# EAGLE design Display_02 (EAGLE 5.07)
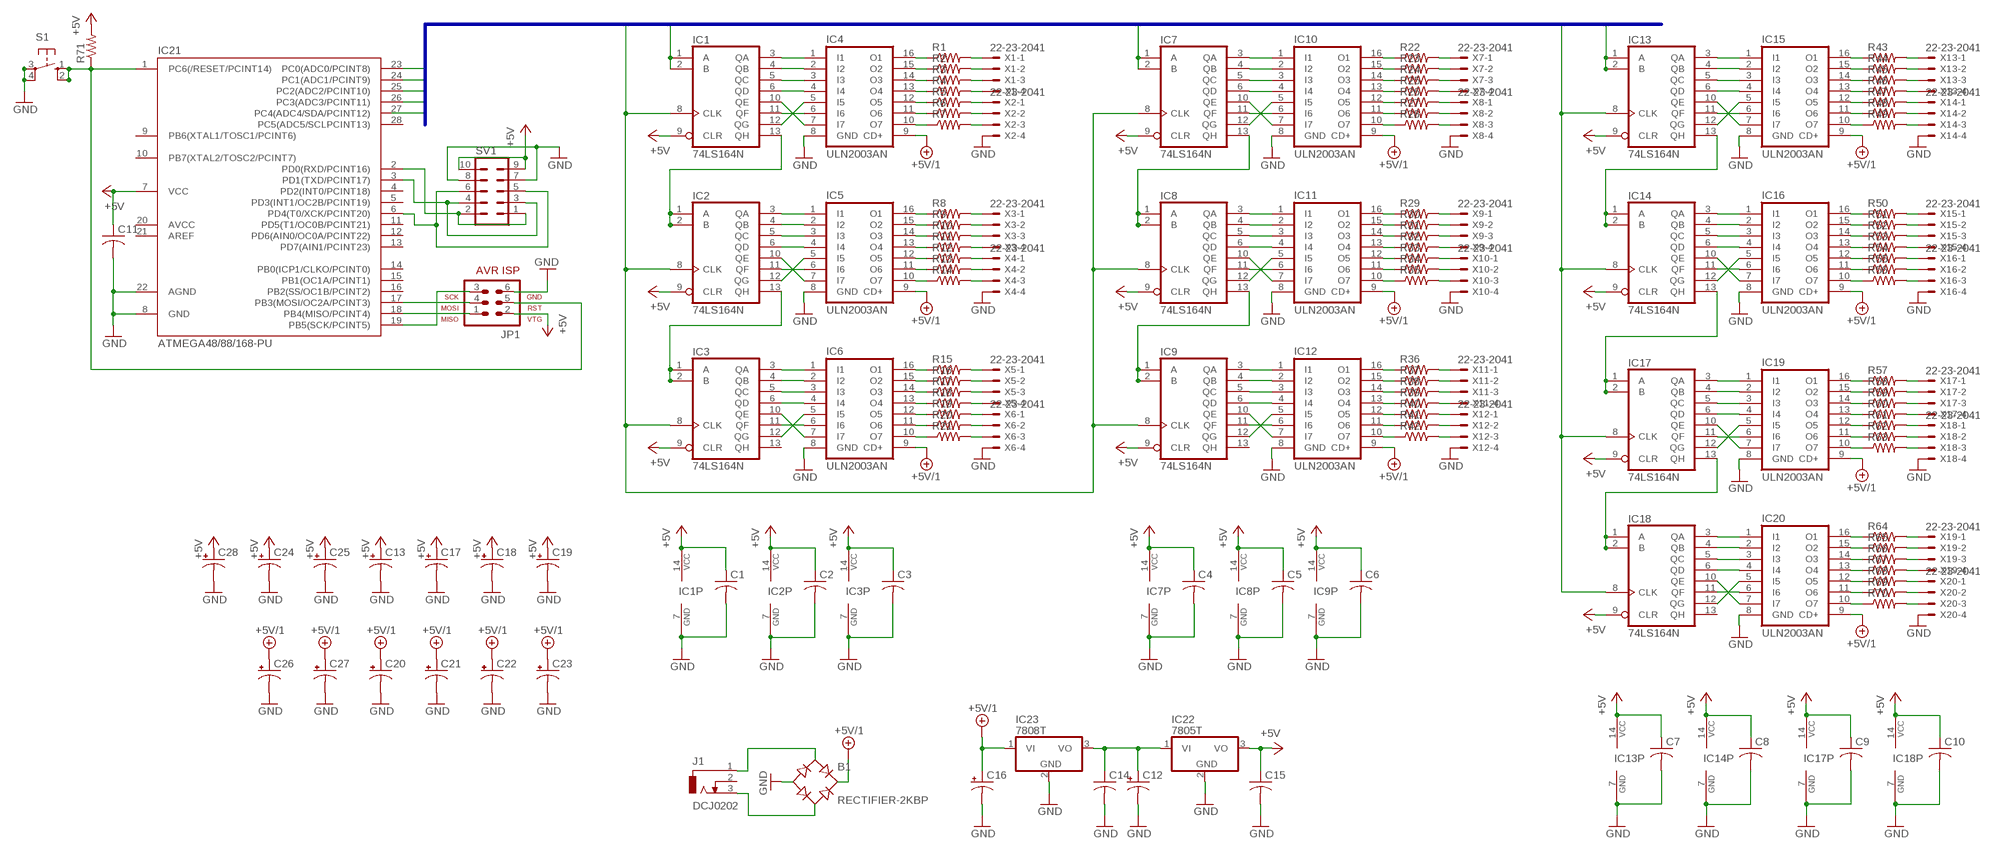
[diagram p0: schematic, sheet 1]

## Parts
B1  RECTIFIER-2KBP  [2KBP]
C1  C-US025-024X044  [C025-024X044]
C2  C-US025-024X044  [C025-024X044]
C3  C-US025-024X044  [C025-024X044]
C4  C-US025-024X044  [C025-024X044]
C5  C-US025-024X044  [C025-024X044]
C6  C-US025-024X044  [C025-024X044]
C7  C-US025-024X044  [C025-024X044]
C8  C-US025-024X044  [C025-024X044]
C9  C-US025-024X044  [C025-024X044]
C10  C-US025-024X044  [C025-024X044]
C11  C-US025-025X050  [C025-025X050]
C12  CPOL-USE2.5-7  [E2,5-7]
C13  CPOL-USE2.5-7  [E2,5-7]
C14  C-US025-030X050  [C025-030X050]
C15  C-US025-030X050  [C025-030X050]
C16  CPOL-USE2.5-7  [E2,5-7]
C17  CPOL-USE2.5-7  [E2,5-7]
C18  CPOL-USE2.5-7  [E2,5-7]
C19  CPOL-USE2.5-7  [E2,5-7]
C20  CPOL-USE2.5-7  [E2,5-7]
C21  CPOL-USE2.5-7  [E2,5-7]
C22  CPOL-USE2.5-7  [E2,5-7]
C23  CPOL-USE2.5-7  [E2,5-7]
C24  CPOL-USE2.5-7  [E2,5-7]
C25  CPOL-USE2.5-7  [E2,5-7]
C26  CPOL-USE2.5-7  [E2,5-7]
C27  CPOL-USE2.5-7  [E2,5-7]
C28  CPOL-USE2.5-7  [E2,5-7]
IC1  74LS164N  [DIL14]
IC2  74LS164N  [DIL14]
IC3  74LS164N  [DIL14]
IC4  ULN2003AN  [DIL16]
IC5  ULN2003AN  [DIL16]
IC6  ULN2003AN  [DIL16]
IC7  74LS164N  [DIL14]
IC8  74LS164N  [DIL14]
IC9  74LS164N  [DIL14]
IC10  ULN2003AN  [DIL16]
IC11  ULN2003AN  [DIL16]
IC12  ULN2003AN  [DIL16]
IC13  74LS164N  [DIL14]
IC14  74LS164N  [DIL14]
IC15  ULN2003AN  [DIL16]
IC16  ULN2003AN  [DIL16]
IC17  74LS164N  [DIL14]
IC18  74LS164N  [DIL14]
IC19  ULN2003AN  [DIL16]
IC20  ULN2003AN  [DIL16]
IC21  ATMEGA48/88/168-PU  [DIL28-3]
IC22  7805T  [TO220H]
IC23  7808T  [TO220H]
J1  DCJ0202  [DCJ0202]
JP1  AVR-ISP-6  [AVR-ISP-6]
R1  R-US_0204/7  [0204/7]
R2  R-US_0204/7  [0204/7]
R3  R-US_0204/7  [0204/7]
R4  R-US_0204/7  [0204/7]
R5  R-US_0204/7  [0204/7]
R6  R-US_0204/7  [0204/7]
R7  R-US_0204/7  [0204/7]
R8  R-US_0204/7  [0204/7]
R9  R-US_0204/7  [0204/7]
R10  R-US_0204/7  [0204/7]
R11  R-US_0204/7  [0204/7]
R12  R-US_0204/7  [0204/7]
R13  R-US_0204/7  [0204/7]
R14  R-US_0204/7  [0204/7]
R15  R-US_0204/7  [0204/7]
R16  R-US_0204/7  [0204/7]
R17  R-US_0204/7  [0204/7]
R18  R-US_0204/7  [0204/7]
R19  R-US_0204/7  [0204/7]
R20  R-US_0204/7  [0204/7]
R21  R-US_0204/7  [0204/7]
R22  R-US_0204/7  [0204/7]
R23  R-US_0204/7  [0204/7]
R24  R-US_0204/7  [0204/7]
R25  R-US_0204/7  [0204/7]
R26  R-US_0204/7  [0204/7]
R27  R-US_0204/7  [0204/7]
R28  R-US_0204/7  [0204/7]
R29  R-US_0204/7  [0204/7]
R30  R-US_0204/7  [0204/7]
R31  R-US_0204/7  [0204/7]
R32  R-US_0204/7  [0204/7]
R33  R-US_0204/7  [0204/7]
R34  R-US_0204/7  [0204/7]
R35  R-US_0204/7  [0204/7]
R36  R-US_0204/7  [0204/7]
R37  R-US_0204/7  [0204/7]
R38  R-US_0204/7  [0204/7]
R39  R-US_0204/7  [0204/7]
R40  R-US_0204/7  [0204/7]
R41  R-US_0204/7  [0204/7]
R42  R-US_0204/7  [0204/7]
R43  R-US_0204/7  [0204/7]
R44  R-US_0204/7  [0204/7]
R45  R-US_0204/7  [0204/7]
R46  R-US_0204/7  [0204/7]
R47  R-US_0204/7  [0204/7]
R48  R-US_0204/7  [0204/7]
R49  R-US_0204/7  [0204/7]
R50  R-US_0204/7  [0204/7]
R51  R-US_0204/7  [0204/7]
R52  R-US_0204/7  [0204/7]
R53  R-US_0204/7  [0204/7]
R54  R-US_0204/7  [0204/7]
R55  R-US_0204/7  [0204/7]
R56  R-US_0204/7  [0204/7]
R57  R-US_0204/7  [0204/7]
R58  R-US_0204/7  [0204/7]
R59  R-US_0204/7  [0204/7]
R60  R-US_0204/7  [0204/7]
R61  R-US_0204/7  [0204/7]
R62  R-US_0204/7  [0204/7]
R63  R-US_0204/7  [0204/7]
R64  R-US_0204/7  [0204/7]
R65  R-US_0204/7  [0204/7]
R66  R-US_0204/7  [0204/7]
R67  R-US_0204/7  [0204/7]
R68  R-US_0204/7  [0204/7]
R69  R-US_0204/7  [0204/7]
R70  R-US_0204/7  [0204/7]
R71  R-US_0204/7  [0204/7]
S1  10-XX  [B3F-10XX]
SV1  MA05-2  [MA05-2]
X1  22-23-2041  [22-23-2041]
X2  22-23-2041  [22-23-2041]
X3  22-23-2041  [22-23-2041]
X4  22-23-2041  [22-23-2041]
X5  22-23-2041  [22-23-2041]
X6  22-23-2041  [22-23-2041]
X7  22-23-2041  [22-23-2041]
X8  22-23-2041  [22-23-2041]
X9  22-23-2041  [22-23-2041]
X10  22-23-2041  [22-23-2041]
X11  22-23-2041  [22-23-2041]
X12  22-23-2041  [22-23-2041]
X13  22-23-2041  [22-23-2041]
X14  22-23-2041  [22-23-2041]
X15  22-23-2041  [22-23-2041]
X16  22-23-2041  [22-23-2041]
X17  22-23-2041  [22-23-2041]
X18  22-23-2041  [22-23-2041]
X19  22-23-2041  [22-23-2041]
X20  22-23-2041  [22-23-2041]

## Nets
+5V: C1.1 C2.1 C3.1 C4.1 C5.1 C6.1 C7.1 C8.1 C9.1 C10.1 C11.1 C13.+ C15.1 C17.+ C18.+ C19.+ C24.+ C25.+ C28.+ IC1.9(CLR) IC1.14(VCC) IC2.9(CLR) IC2.14(VCC) IC3.9(CLR) IC3.14(VCC) IC7.9(CLR) IC7.14(VCC) IC8.9(CLR) IC8.14(VCC) IC9.9(CLR) IC9.14(VCC) IC13.9(CLR) IC13.14(VCC) IC14.9(CLR) IC14.14(VCC) IC17.9(CLR) IC17.14(VCC) IC18.9(CLR) IC18.14(VCC) IC21.7(VCC) IC22.3(VO) JP1.2 R71.2 SV1.9 SV1.10
+5V/1: B1.+ C16.+ C20.+ C21.+ C22.+ C23.+ C26.+ C27.+ IC4.9(CD+) IC5.9(CD+) IC6.9(CD+) IC10.9(CD+) IC11.9(CD+) IC12.9(CD+) IC15.9(CD+) IC16.9(CD+) IC19.9(CD+) IC20.9(CD+) IC23.1(VI)
GND: B1.- C1.2 C2.2 C3.2 C4.2 C5.2 C6.2 C7.2 C8.2 C9.2 C10.2 C11.2 C12.- C13.- C14.2 C15.2 C16.- C17.- C18.- C19.- C20.- C21.- C22.- C23.- C24.- C25.- C26.- C27.- C28.- IC1.7(GND) IC2.7(GND) IC3.7(GND) IC4.8(GND) IC5.8(GND) IC6.8(GND) IC7.7(GND) IC8.7(GND) IC9.7(GND) IC10.8(GND) IC11.8(GND) IC12.8(GND) IC13.7(GND) IC14.7(GND) IC15.8(GND) IC16.8(GND) IC17.7(GND) IC18.7(GND) IC19.8(GND) IC20.8(GND) IC21.8(GND) IC21.22(AGND) IC22.2(GND) IC23.2(GND) JP1.6 S1.3(P) S1.4(P1) SV1.7 SV1.8 X2.4 X4.4 X6.4 X8.4 X10.4 X12.4 X14.4 X16.4 X18.4 X20.4
N$1: IC1.3(QA) IC4.1(I1)
N$2: IC1.4(QB) IC4.2(I2)
N$3: IC1.5(QC) IC4.3(I3)
N$4: IC1.6(QD) IC4.4(I4)
N$5: IC1.10(QE) IC4.7(I7)
N$6: IC1.11(QF) IC4.6(I6)
N$7: IC1.12(QG) IC4.5(I5)
N$8: IC2.3(QA) IC5.1(I1)
N$9: IC2.4(QB) IC5.2(I2)
N$10: IC2.5(QC) IC5.3(I3)
N$11: IC2.6(QD) IC5.4(I4)
N$12: IC2.10(QE) IC5.7(I7)
N$13: IC2.12(QG) IC5.5(I5)
N$14: IC2.11(QF) IC5.6(I6)
N$15: IC3.3(QA) IC6.1(I1)
N$16: IC3.4(QB) IC6.2(I2)
N$17: IC4.16(O1) R1.1
N$18: IC4.15(O2) R2.1
N$19: IC4.14(O3) R3.1
N$20: IC4.13(O4) R4.1
N$21: IC4.12(O5) R5.1
N$22: IC4.11(O6) R6.1
N$23: IC4.10(O7) R7.1
N$24: R1.2 X1.1
N$25: R2.2 X1.2
N$26: R3.2 X1.3
N$27: R4.2 X1.4
N$28: R5.2 X2.1
N$29: R6.2 X2.2
N$30: R7.2 X2.3
N$31: IC5.16(O1) R8.1
N$32: IC5.15(O2) R9.1
N$33: IC5.14(O3) R10.1
N$34: IC5.13(O4) R11.1
N$35: IC5.12(O5) R12.1
N$36: IC5.11(O6) R13.1
N$37: IC5.10(O7) R14.1
N$38: R8.2 X3.1
N$39: R9.2 X3.2
N$40: R10.2 X3.3
N$41: R11.2 X3.4
N$42: R12.2 X4.1
N$43: R13.2 X4.2
N$44: R14.2 X4.3
N$45: IC6.16(O1) R15.1
N$46: IC6.15(O2) R16.1
N$47: IC6.14(O3) R17.1
N$48: IC6.13(O4) R18.1
N$49: IC6.12(O5) R19.1
N$50: IC6.11(O6) R20.1
N$51: IC6.10(O7) R21.1
N$52: R15.2 X5.1
N$53: R16.2 X5.2
N$54: R17.2 X5.3
N$55: R18.2 X5.4
N$56: R19.2 X6.1
N$57: R20.2 X6.2
N$58: R21.2 X6.3
N$59: IC21.2(PD0(RXD/PCINT16)) SV1.1 SV1.2
N$60: IC21.3(PD1(TXD/PCINT17)) SV1.3 SV1.4
N$61: IC3.5(QC) IC6.3(I3)
N$62: IC3.6(QD) IC6.4(I4)
N$63: IC3.10(QE) IC6.7(I7)
N$64: IC3.12(QG) IC6.5(I5)
N$65: IC3.11(QF) IC6.6(I6)
N$66: IC10.16(O1) R22.1
N$67: IC2.13(QH) IC3.1(A) IC3.2(B)
N$68: IC1.13(QH) IC2.1(A) IC2.2(B)
N$69: IC10.15(O2) R23.1
N$70: IC10.14(O3) R24.1
N$71: IC10.13(O4) R25.1
N$72: IC10.12(O5) R26.1
N$73: IC10.11(O6) R27.1
N$74: IC10.10(O7) R28.1
N$75: R22.2 X7.1
N$76: R23.2 X7.2
N$77: R24.2 X7.3
N$78: R25.2 X7.4
N$79: R26.2 X8.1
N$80: R27.2 X8.2
N$81: R28.2 X8.3
N$82: IC11.16(O1) R29.1
N$83: IC11.15(O2) R30.1
N$84: IC11.14(O3) R31.1
N$85: IC11.13(O4) R32.1
N$86: IC11.12(O5) R33.1
N$87: IC11.11(O6) R34.1
N$88: IC11.10(O7) R35.1
N$89: R29.2 X9.1
N$90: R30.2 X9.2
N$91: R31.2 X9.3
N$92: R32.2 X9.4
N$93: R33.2 X10.1
N$94: R34.2 X10.2
N$95: R35.2 X10.3
N$96: IC12.16(O1) R36.1
N$97: IC12.15(O2) R37.1
N$98: IC12.14(O3) R38.1
N$99: IC12.13(O4) R39.1
N$100: IC12.12(O5) R40.1
N$101: IC12.11(O6) R41.1
N$102: IC12.10(O7) R42.1
N$103: R36.2 X11.1
N$104: R37.2 X11.2
N$105: R38.2 X11.3
N$106: R39.2 X11.4
N$107: R40.2 X12.1
N$108: R41.2 X12.2
N$109: R42.2 X12.3
N$110: IC8.13(QH) IC9.1(A) IC9.2(B)
N$111: IC7.13(QH) IC8.1(A) IC8.2(B)
N$112: IC15.16(O1) R43.1
N$113: IC21.6(PD4(T0/XCK/PCINT20)) SV1.5 SV1.6
N$114: IC7.6(QD) IC10.4(I4)
N$115: IC7.5(QC) IC10.3(I3)
N$116: IC7.4(QB) IC10.2(I2)
N$117: IC7.3(QA) IC10.1(I1)
N$118: IC7.10(QE) IC10.7(I7)
N$119: IC7.11(QF) IC10.6(I6)
N$120: IC7.12(QG) IC10.5(I5)
N$121: IC8.3(QA) IC11.1(I1)
N$122: IC8.4(QB) IC11.2(I2)
N$123: IC8.5(QC) IC11.3(I3)
N$124: IC8.6(QD) IC11.4(I4)
N$125: IC8.10(QE) IC11.7(I7)
N$126: IC8.12(QG) IC11.5(I5)
N$127: IC8.11(QF) IC11.6(I6)
N$128: IC9.3(QA) IC12.1(I1)
N$129: IC9.4(QB) IC12.2(I2)
N$130: IC9.5(QC) IC12.3(I3)
N$131: IC9.6(QD) IC12.4(I4)
N$132: IC9.10(QE) IC12.7(I7)
N$133: IC9.12(QG) IC12.5(I5)
N$134: IC9.11(QF) IC12.6(I6)
N$135: IC15.15(O2) R44.1
N$136: IC15.14(O3) R45.1
N$137: IC15.13(O4) R46.1
N$138: IC15.12(O5) R47.1
N$139: IC15.11(O6) R48.1
N$140: IC15.10(O7) R49.1
N$141: R43.2 X13.1
N$142: R44.2 X13.2
N$143: R45.2 X13.3
N$144: R46.2 X13.4
N$145: R47.2 X14.1
N$146: R48.2 X14.2
N$147: R49.2 X14.3
N$148: IC16.16(O1) R50.1
N$149: IC16.15(O2) R51.1
N$150: IC16.14(O3) R52.1
N$151: IC16.13(O4) R53.1
N$152: IC16.12(O5) R54.1
N$153: IC16.11(O6) R55.1
N$154: IC16.10(O7) R56.1
N$155: R50.2 X15.1
N$156: R51.2 X15.2
N$157: R52.2 X15.3
N$158: R53.2 X15.4
N$159: R54.2 X16.1
N$160: R55.2 X16.2
N$161: R56.2 X16.3
N$162: IC13.13(QH) IC14.1(A) IC14.2(B)
N$165: IC13.10(QE) IC15.7(I7)
N$166: IC13.12(QG) IC15.5(I5)
N$167: IC13.11(QF) IC15.6(I6)
N$168: IC14.10(QE) IC16.7(I7)
N$169: IC14.12(QG) IC16.5(I5)
N$170: IC14.11(QF) IC16.6(I6)
N$171: IC13.3(QA) IC15.1(I1)
N$172: IC13.4(QB) IC15.2(I2)
N$173: IC13.5(QC) IC15.3(I3)
N$174: IC13.6(QD) IC15.4(I4)
N$175: IC14.3(QA) IC16.1(I1)
N$176: IC14.4(QB) IC16.2(I2)
N$177: IC14.5(QC) IC16.3(I3)
N$178: IC14.6(QD) IC16.4(I4)
N$179: IC19.16(O1) R57.1
N$180: IC19.15(O2) R58.1
N$181: IC19.14(O3) R59.1
N$182: IC19.13(O4) R60.1
N$183: IC19.12(O5) R61.1
N$184: IC19.11(O6) R62.1
N$185: IC19.10(O7) R63.1
N$186: R57.2 X17.1
N$187: R58.2 X17.2
N$188: R59.2 X17.3
N$189: R60.2 X17.4
N$190: R61.2 X18.1
N$191: R62.2 X18.2
N$192: R63.2 X18.3
N$193: IC20.16(O1) R64.1
N$194: IC20.15(O2) R65.1
N$195: IC20.14(O3) R66.1
N$196: IC20.13(O4) R67.1
N$197: IC20.12(O5) R68.1
N$198: IC20.11(O6) R69.1
N$199: IC20.10(O7) R70.1
N$200: R64.2 X19.1
N$201: R65.2 X19.2
N$202: R66.2 X19.3
N$203: R67.2 X19.4
N$204: R68.2 X20.1
N$205: R69.2 X20.2
N$206: R70.2 X20.3
N$207: IC17.13(QH) IC18.1(A) IC18.2(B)
N$208: IC14.13(QH) IC17.1(A) IC17.2(B)
N$209: IC21.18(PB4(MISO/PCINT4)) JP1.1
N$210: IC17.10(QE) IC19.7(I7)
N$211: IC17.12(QG) IC19.5(I5)
N$212: IC17.11(QF) IC19.6(I6)
N$213: IC18.10(QE) IC20.7(I7)
N$214: IC18.12(QG) IC20.5(I5)
N$215: IC18.11(QF) IC20.6(I6)
N$216: IC17.3(QA) IC19.1(I1)
N$217: IC17.4(QB) IC19.2(I2)
N$218: IC17.5(QC) IC19.3(I3)
N$219: IC17.6(QD) IC19.4(I4)
N$220: IC18.3(QA) IC20.1(I1)
N$221: IC18.4(QB) IC20.2(I2)
N$222: IC18.5(QC) IC20.3(I3)
N$223: IC18.6(QD) IC20.4(I4)
N$224: IC21.17(PB3(MOSI/OC2A/PCINT3)) JP1.4
N$225: IC21.19(PB5(SCK/PCINT5)) JP1.3
N$226: IC21.1(PC6(/RESET/PCINT14)) JP1.5 R71.1 S1.1(S) S1.2(S1)
N$227: C12.+ C14.1 IC22.1(VI) IC23.3(VO)
N$228: B1.AC2 J1.3
N$229: B1.AC1 J1.1
PORTC0: IC13.1(A) IC13.2(B) IC21.23(PC0(ADC0/PCINT8))
PORTC1: IC13.8(CLK) IC14.8(CLK) IC17.8(CLK) IC18.8(CLK) IC21.24(PC1(ADC1/PCINT9))
PORTC2: IC7.1(A) IC7.2(B) IC21.25(PC2(ADC2/PCINT10))
PORTC3: IC1.1(A) IC1.2(B) IC21.26(PC3(ADC3/PCINT11))
PORTC4: IC1.8(CLK) IC2.8(CLK) IC3.8(CLK) IC7.8(CLK) IC8.8(CLK) IC9.8(CLK)
Unconnected: IC3.13(QH) IC9.13(QH) IC18.13(QH) IC21.4(PD2(INT0/PCINT18)) IC21.5(PD3(INT1/OC2B/PCINT19)) IC21.9(PB6(XTAL1/TOSC1/PCINT6)) IC21.10(PB7(XTAL2/TOSC2/PCINT7)) IC21.11(PD5(T1/OC0B/PCINT21)) IC21.12(PD6(AIN0/OC0A/PCINT22)) IC21.13(PD7(AIN1/PCINT23)) IC21.14(PB0(ICP1/CLKO/PCINT0)) IC21.15(PB1(OC1A/PCINT1)) IC21.16(PB2(SS/OC1B/PCINT2)) IC21.20(AVCC) IC21.21(AREF) IC21.27(PC4(ADC4/SDA/PCINT12)) IC21.28(PC5(ADC5/SCLPCINT13)) J1.2

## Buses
PORTC[0..5]

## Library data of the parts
B1 = rectifier:RECTIFIER-: Rectifier
C1-C10 C14 C15 = rcl:C-US: CAPACITOR, American symbol
C11 = resistor:C-US: CAPACITOR, American symbol
C12 C13 C16-C28 = rcl:CPOL-US: POLARIZED CAPACITOR, American symbol
IC1-IC3 IC7-IC9 IC13 IC14 IC17 IC18 = 74xx-us:74*164: 8-bit parallel out SHIFT REGISTER
IC4-IC6 IC10-IC12 IC15 IC16 IC19 IC20 = uln-udn:ULN2003A: DRIVER ARRAY
IC21 = atmega8:ATMEGA48/88/168-PU
IC22 IC23 = linear:78*: Positive VOLTAGE REGULATOR Source: http://cache.national.com/ds/LM/LM78L05.pdf http://www.fairchildsemi.com/ds/LM/LM7805.pdf
J1 = con-jack:DCJ0202: DC POWER JACK Source: DCJ0202.pdf
JP1 = avr-6:AVR-ISP-6: AVR ISP-6 Serial Programming Header
R1-R71 = rcl:R-US_: RESISTOR, American symbol
S1 = switch-omron:10-XX: OMRON SWITCH
SV1 = con-lstb:MA05-2: PIN HEADER
X1-X20 = con-molex:22-23-2041: .100" (2.54mm) Center Header - 4 Pin

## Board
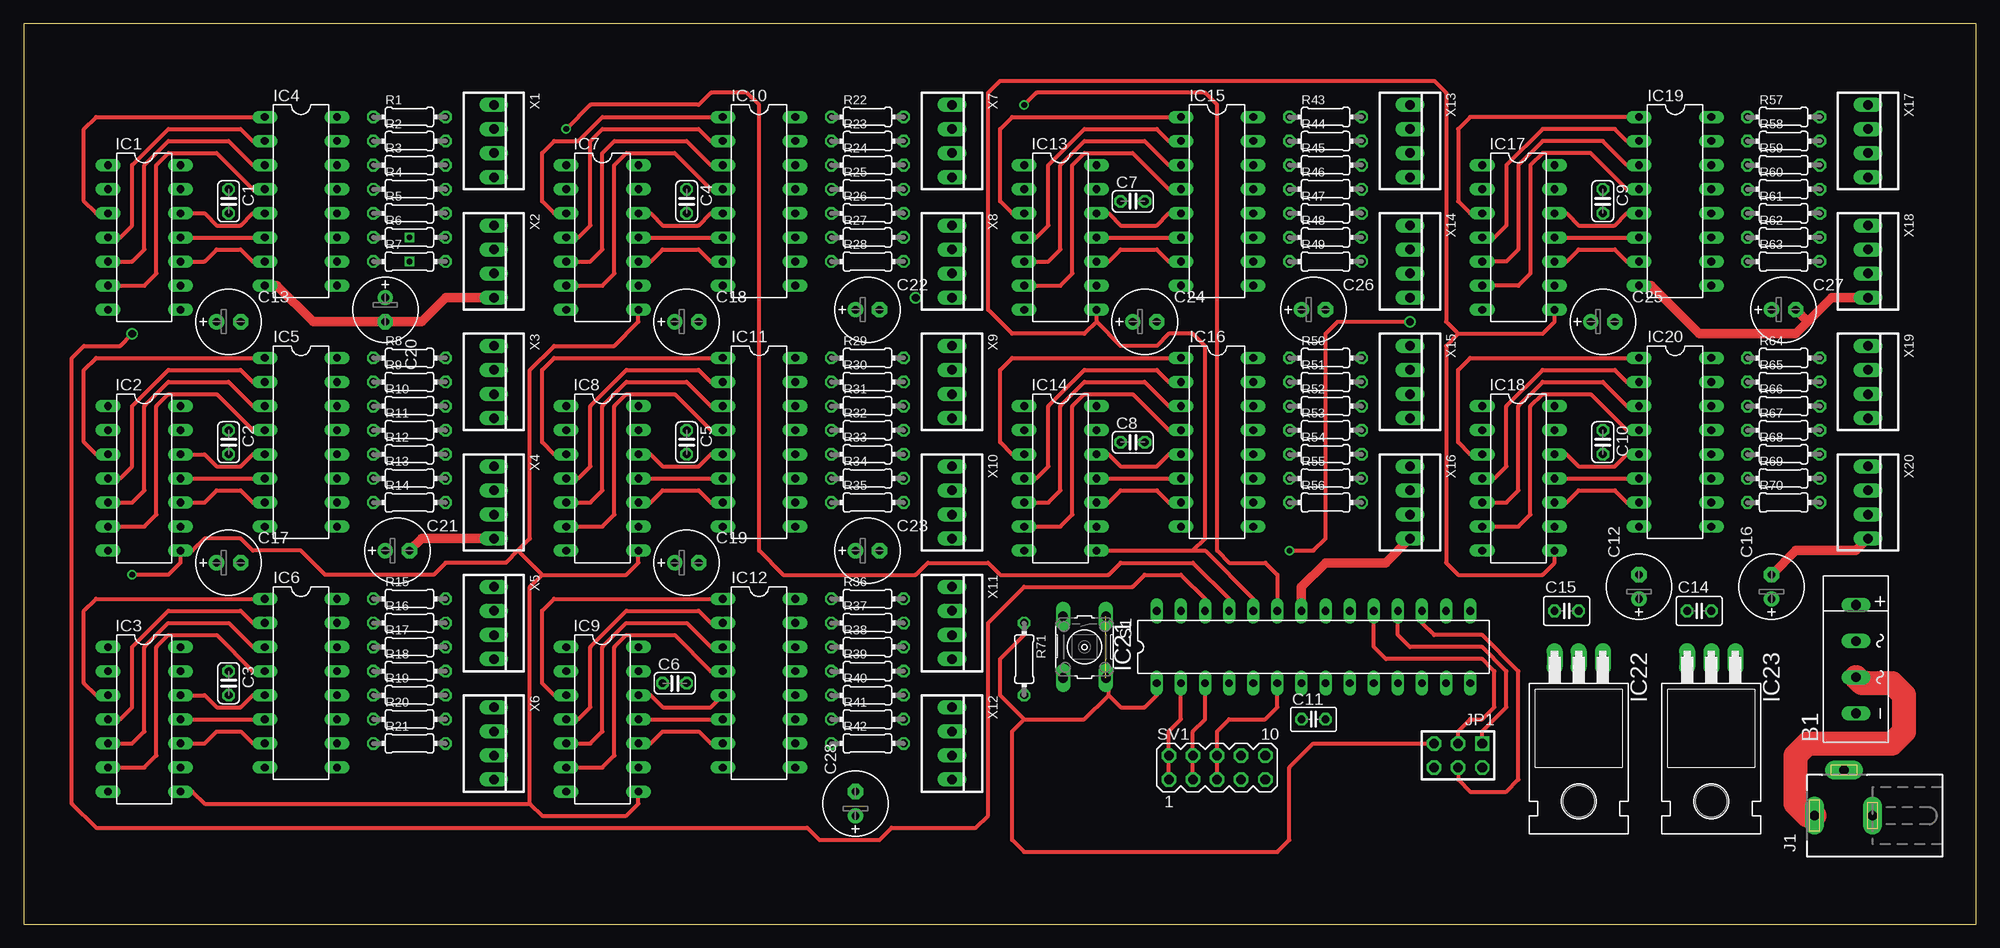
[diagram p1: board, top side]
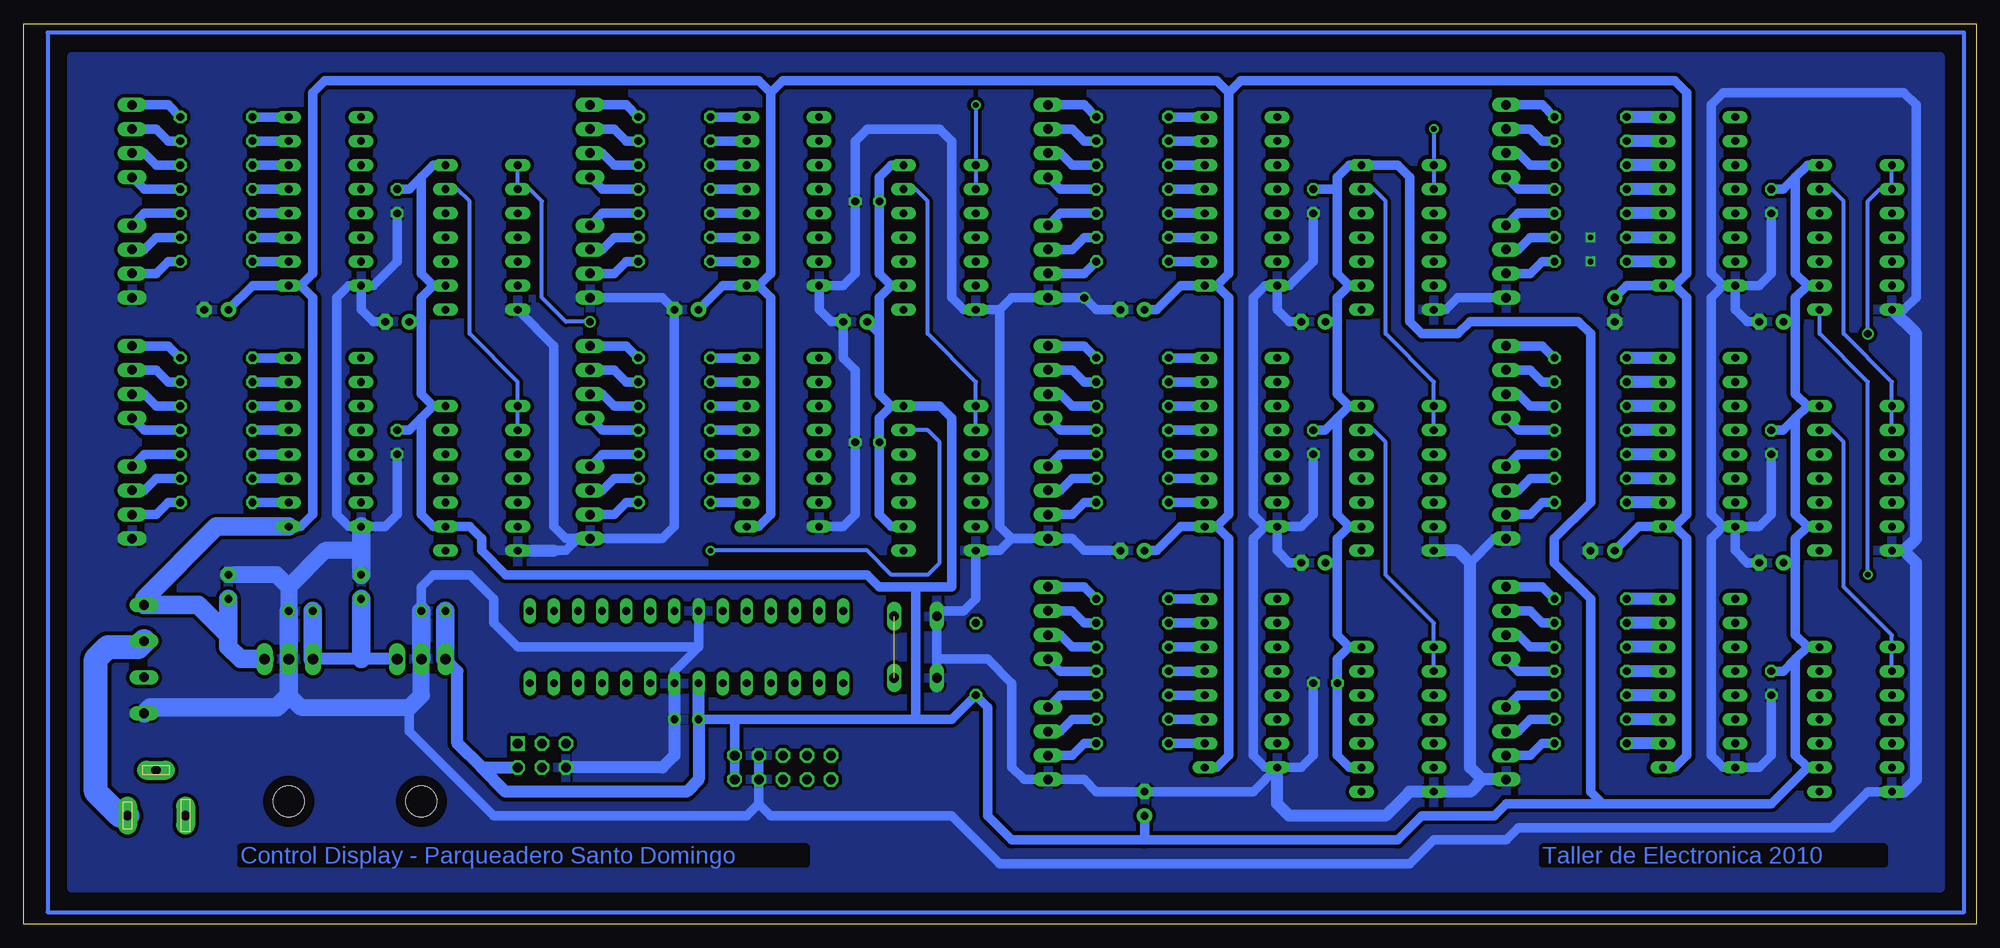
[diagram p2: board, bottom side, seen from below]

Size 205.72 x 94.92 mm. Coordinates in mm from the lower left corner, seen from the top.
Outline: 0,0 205.72,0 205.72,94.92 0,94.92 0,0
Copper layers (1*16): Top 0.035mm / dielectric 1.5mm / Bottom 0.035mm
Design rules "default *": minimum track width 15mil, minimum drill 24mil, track to track 15mil, track to pad 15mil, pad to pad 15mil, via to via 15mil, smd to smd 8mil, copper to edge 40mil, drill to drill 8mil, minimum pad ring 10mil, minimum via ring 8mil, stop-mask expansion 4mil, vias tented up to drill 0mil, thermal gap 10mil

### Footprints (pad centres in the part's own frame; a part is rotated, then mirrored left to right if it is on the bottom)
2KBP = drill 1.016 long: + 5.715,0; - -5.715,0; AC1 -1.905,0; AC2 1.905,0
C025-024X044 = drill 0.813 octagon: 1 -1.27,0; 2 1.27,0
C025-025X050 = drill 0.813 octagon: 1 -1.27,0; 2 1.27,0
E2,5-7 = drill 0.813 pad 1.6 round: + -1.27,0 | drill 0.813 pad 1.6 octagon: - 1.27,0
C025-030X050 = drill 0.813 octagon: 1 -1.27,0; 2 1.27,0
DIL14 = drill 0.813 long: 1 -7.62,-3.81; 2 -5.08,-3.81; 3 -2.54,-3.81; 4 0,-3.81; 5 2.54,-3.81; 6 5.08,-3.81; 7 7.62,-3.81; 8 7.62,3.81; 9 5.08,3.81; 10 2.54,3.81; 11 0,3.81; 12 -2.54,3.81; 13 -5.08,3.81; 14 -7.62,3.81
DIL16 = drill 0.813 long: 1 -8.89,-3.81; 2 -6.35,-3.81; 3 -3.81,-3.81; 4 -1.27,-3.81; 5 1.27,-3.81; 6 3.81,-3.81; 7 6.35,-3.81; 8 8.89,-3.81; 9 8.89,3.81; 10 6.35,3.81; 11 3.81,3.81; 12 1.27,3.81; 13 -1.27,3.81; 14 -3.81,3.81; 15 -6.35,3.81; 16 -8.89,3.81
DIL28-3 = drill 0.813 long: 1 -16.51,-3.81; 2 -13.97,-3.81; 3 -11.43,-3.81; 4 -8.89,-3.81; 5 -6.35,-3.81; 6 -3.81,-3.81; 7 -1.27,-3.81; 8 1.27,-3.81; 9 3.81,-3.81; 10 6.35,-3.81; 11 8.89,-3.81; 12 11.43,-3.81; 13 13.97,-3.81; 14 16.51,-3.81; 15 16.51,3.81; 16 13.97,3.81; 17 11.43,3.81; 18 8.89,3.81; 19 6.35,3.81; 20 3.81,3.81; 21 1.27,3.81; 22 -1.27,3.81; 23 -3.81,3.81; 24 -6.35,3.81; 25 -8.89,3.81; 26 -11.43,3.81; 27 -13.97,3.81; 28 -16.51,3.81
TO220H = drill 1.118 long: 1 -2.54,-10.16; 2 0,-10.16; 3 2.54,-10.16 | hole 3.302: 0,4.826
DCJ0202 = drill 1 pad 2 long: 1 0,3.1; 2 4.8,0; 3 0,-3
AVR-ISP-6 = drill 1.016 square: 1 -2.54,-1.27 | drill 1.016 octagon: 2 -2.54,1.27; 3 0,-1.27; 4 0,1.27; 5 2.54,-1.27; 6 2.54,1.27
0204/7 = drill 0.813 octagon: 1 -3.81,0; 2 3.81,0
B3F-10XX = drill 1.016 long: 1 -3.251,2.261; 2 3.251,2.261; 3 -3.251,-2.261; 4 3.251,-2.261
MA05-2 = drill 1.016 octagon: 1 -5.08,-1.27; 2 -5.08,1.27; 3 -2.54,-1.27; 4 -2.54,1.27; 5 0,-1.27; 6 0,1.27; 7 2.54,-1.27; 8 2.54,1.27; 9 5.08,-1.27; 10 5.08,1.27
22-23-2041 = drill 1 long: 1 -3.81,0; 2 -1.27,0; 3 1.27,0; 4 3.81,0

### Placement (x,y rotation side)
B1  193.04,27.94 90 top
C1  21.59,76.2 270 top
C2  21.59,50.8 270 top
C3  21.59,25.4 270 top
C4  69.85,76.2 270 top
C5  69.85,50.8 270 top
C6  68.58,25.4 0 top
C7  116.84,76.2 0 top
C8  116.84,50.8 0 top
C9  166.37,76.2 270 top
C10  166.37,50.8 270 top
C11  135.89,21.59 0 top
C12  170.18,35.56 90 top
C13  21.59,63.5 0 top
C14  176.53,33.02 0 top
C15  162.56,33.02 0 top
C16  184.15,35.56 90 top
C17  21.59,38.1 0 top
C18  69.85,63.5 0 top
C19  69.85,38.1 0 top
C20  38.1,64.77 270 top
C21  39.37,39.37 0 top
C22  88.9,64.77 0 top
C23  88.9,39.37 0 top
C24  118.11,63.5 0 top
C25  166.37,63.5 0 top
C26  135.89,64.77 0 top
C27  185.42,64.77 0 top
C28  87.63,12.7 90 top
IC1  12.7,72.39 270 top
IC2  12.7,46.99 270 top
IC3  12.7,21.59 270 top
IC4  29.21,76.2 270 top
IC5  29.21,50.8 270 top
IC6  29.21,25.4 270 top
IC7  60.96,72.39 270 top
IC8  60.96,46.99 270 top
IC9  60.96,21.59 270 top
IC10  77.47,76.2 270 top
IC11  77.47,50.8 270 top
IC12  77.47,25.4 270 top
IC13  109.22,72.39 270 top
IC14  109.22,46.99 270 top
IC15  125.73,76.2 270 top
IC16  125.73,50.8 270 top
IC17  157.48,72.39 270 top
IC18  157.48,46.99 270 top
IC19  173.99,76.2 270 top
IC20  173.99,50.8 270 top
IC21  135.89,29.21 0 top
IC22  163.83,17.78 180 top
IC23  177.8,17.78 180 top
J1  191.77,11.43 90 top
JP1  151.13,17.78 180 top
R1  40.64,85.09 0 top
R2  40.64,82.55 0 top
R3  40.64,80.01 0 top
R4  40.64,77.47 0 top
R5  40.64,74.93 0 top
R6  40.64,72.39 0 top
R7  40.64,69.85 0 top
R8  40.64,59.69 0 top
R9  40.64,57.15 0 top
R10  40.64,54.61 0 top
R11  40.64,52.07 0 top
R12  40.64,49.53 0 top
R13  40.64,46.99 0 top
R14  40.64,44.45 0 top
R15  40.64,34.29 0 top
R16  40.64,31.75 0 top
R17  40.64,29.21 0 top
R18  40.64,26.67 0 top
R19  40.64,24.13 0 top
R20  40.64,21.59 0 top
R21  40.64,19.05 0 top
R22  88.9,85.09 0 top
R23  88.9,82.55 0 top
R24  88.9,80.01 0 top
R25  88.9,77.47 0 top
R26  88.9,74.93 0 top
R27  88.9,72.39 0 top
R28  88.9,69.85 0 top
R29  88.9,59.69 0 top
R30  88.9,57.15 0 top
R31  88.9,54.61 0 top
R32  88.9,52.07 0 top
R33  88.9,49.53 0 top
R34  88.9,46.99 0 top
R35  88.9,44.45 0 top
R36  88.9,34.29 0 top
R37  88.9,31.75 0 top
R38  88.9,29.21 0 top
R39  88.9,26.67 0 top
R40  88.9,24.13 0 top
R41  88.9,21.59 0 top
R42  88.9,19.05 0 top
R43  137.16,85.09 0 top
R44  137.16,82.55 0 top
R45  137.16,80.01 0 top
R46  137.16,77.47 0 top
R47  137.16,74.93 0 top
R48  137.16,72.39 0 top
R49  137.16,69.85 0 top
R50  137.16,59.69 0 top
R51  137.16,57.15 0 top
R52  137.16,54.61 0 top
R53  137.16,52.07 0 top
R54  137.16,49.53 0 top
R55  137.16,46.99 0 top
R56  137.16,44.45 0 top
R57  185.42,85.09 0 top
R58  185.42,82.55 0 top
R59  185.42,80.01 0 top
R60  185.42,77.47 0 top
R61  185.42,74.93 0 top
R62  185.42,72.39 0 top
R63  185.42,69.85 0 top
R64  185.42,59.69 0 top
R65  185.42,57.15 0 top
R66  185.42,54.61 0 top
R67  185.42,52.07 0 top
R68  185.42,49.53 0 top
R69  185.42,46.99 0 top
R70  185.42,44.45 0 top
R71  105.41,27.94 270 top
S1  111.76,29.21 270 top
SV1  125.73,16.51 0 top
X1  49.53,82.55 270 top
X2  49.53,69.85 270 top
X3  49.53,57.15 270 top
X4  49.53,44.45 270 top
X5  49.53,31.75 270 top
X6  49.53,19.05 270 top
X7  97.79,82.55 270 top
X8  97.79,69.85 270 top
X9  97.79,57.15 270 top
X10  97.79,44.45 270 top
X11  97.79,31.75 270 top
X12  97.79,19.05 270 top
X13  146.05,82.55 270 top
X14  146.05,69.85 270 top
X15  146.05,57.15 270 top
X16  146.05,44.45 270 top
X17  194.31,82.55 270 top
X18  194.31,69.85 270 top
X19  194.31,57.15 270 top
X20  194.31,44.45 270 top

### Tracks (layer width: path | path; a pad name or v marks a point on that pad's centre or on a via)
+5V
  Bottom 1.016: IC13.14 114.3,80.01 115.57,78.74 C7.1 115.57,68.58 114.3,67.31 | 114.3,67.31 IC13.9 | 114.3,67.31 115.57,66.04 115.57,62.23 | 115.57,62.23 115.57,55.88 114.3,54.61 | 162.56,67.31 163.83,68.58 163.83,78.74 | 163.83,78.74 162.56,80.01 IC17.14 | 162.56,67.31 IC17.9 | 162.56,67.31 163.83,66.04 163.83,63.5 | 163.83,63.5 163.83,55.88 162.56,54.61 | 162.56,54.61 IC18.14 | 163.83,53.34 162.56,54.61 | 163.83,53.34 163.83,43.18 162.56,41.91 IC18.9 158.75,41.91 157.48,40.64 157.48,39.37 154.94,36.83 116.84,36.83 115.57,35.56 111.76,35.56 | C10.1 165.1,52.07 163.83,53.34 | IC1.14 17.78,80.01 19.05,78.74 | 19.05,78.74 19.05,68.58 17.78,67.31 | 17.78,67.31 IC1.9 | 17.78,67.31 19.05,66.04 19.05,63.5 | 19.05,63.5 19.05,55.88 17.78,54.61 | 17.78,54.61 IC2.14 | 17.78,41.91 19.05,43.18 19.05,53.34 | 19.05,53.34 17.78,54.61 | IC3.9 17.78,16.51 | 17.78,16.51 19.05,17.78 19.05,27.94 | 19.05,27.94 17.78,29.21 | 17.78,29.21 IC3.14 | 66.04,29.21 IC9.14 | 66.04,41.91 IC8.9 | 66.04,54.61 67.31,53.34 | 66.04,54.61 IC8.14 | 66.04,54.61 67.31,55.88 67.31,63.5 | 67.31,63.5 67.31,66.04 66.04,67.31 | 66.04,67.31 IC7.9 | 66.04,67.31 67.31,68.58 67.31,77.47 | 67.31,77.47 67.31,78.74 66.04,80.01 IC7.14 60.96,80.01 59.69,78.74 59.69,63.5 58.42,62.23 54.61,62.23 53.34,63.5 41.91,63.5 40.64,62.23 40.64,44.45 44.45,40.64 44.45,38.1 40.64,34.29 40.64,13.97 39.37,12.7 | 67.31,77.47 C4.1 | C3.1 20.32,26.67 19.05,27.94 | C2.1 20.32,52.07 19.05,53.34 | C1.1 20.32,77.47 19.05,78.74 | C9.1 165.1,77.47 163.83,78.74 | 17.78,41.91 IC2.9 | 17.78,41.91 19.05,40.64 19.05,38.1 | 19.05,38.1 19.05,30.48 17.78,29.21 | IC14.9 114.3,41.91 115.57,43.18 C8.1 115.57,53.34 114.3,54.61
  Bottom 1.016: 114.3,54.61 IC14.14 109.22,54.61 107.95,53.34 107.95,35.56 111.76,35.56 | 39.37,12.7 21.59,12.7 17.78,16.51 | C5.1 68.58,52.07 67.31,53.34 | 67.31,53.34 67.31,43.18 66.04,41.91 | 66.04,41.91 67.31,40.64 67.31,38.1 | 67.31,38.1 67.31,30.48 66.04,29.21 | 66.04,29.21 67.31,27.94 C6.1 67.31,17.78 66.04,16.51 IC9.9 | 87.63,8.89 60.96,8.89 58.42,11.43 50.8,11.43 49.53,12.7 39.37,12.7 | 87.63,8.89 101.6,8.89 104.14,11.43 104.14,22.86 R71.2 107.95,21.59 111.76,21.59 | 19.05,38.1 C17.+ | 19.05,63.5 C13.+ | 67.31,63.5 C18.+ | 67.31,38.1 C19.+ | 115.57,62.23 C24.+ | 163.83,63.5 C25.+ | 111.76,21.59 130.81,21.59 | 130.81,21.59 C11.1 | 87.63,8.89 C28.+ | SV1.10 SV1.9 130.81,21.59 | 111.76,21.59 111.76,35.56
  Bottom 1.27: 157.48,16.51 160.02,19.05 160.02,26.67 IC22.3 | IC21.7 C11.1 134.62,15.24 135.89,13.97 154.94,13.97 157.48,16.51 | 157.48,16.51 JP1.2
  Bottom 1.93: IC22.3 C15.1
+5V/1
  Bottom 1.016: 80.01,67.31 IC10.9 83.82,67.31 86.36,64.77 C22.+ | 128.27,67.31 127,66.04 127,43.18 128.27,41.91 IC16.9 | 176.53,67.31 IC19.9 181.61,67.31 C27.+ | 176.53,67.31 175.26,66.04 175.26,43.18 176.53,41.91 IC20.9 | 31.75,41.91 IC5.9 35.56,41.91 C21.+ | 31.75,67.31 IC4.9 36.83,67.31 C20.+ | 128.27,67.31 IC15.9 132.08,67.31 C26.+ | 128.27,67.31 127,68.58 127,87.63 | 127,87.63 128.27,88.9 173.99,88.9 175.26,87.63 175.26,68.58 176.53,67.31 | 80.01,41.91 IC11.9 83.82,41.91 86.36,39.37 C23.+ | 80.01,41.91 78.74,43.18 78.74,66.04 80.01,67.31 | 80.01,67.31 78.74,68.58 78.74,87.63 | 78.74,87.63 80.01,88.9 125.73,88.9 127,87.63 | IC6.9 31.75,16.51 30.48,17.78 30.48,40.64 31.75,41.91 | 31.75,41.91 30.48,43.18 30.48,66.04 31.75,67.31 | 31.75,67.31 30.48,68.58 30.48,87.63 31.75,88.9 77.47,88.9 78.74,87.63 | IC12.9 80.01,16.51 78.74,17.78 78.74,40.64 80.01,41.91
  Bottom 1.93: IC23.1 182.88,27.94 184.15,29.21 184.15,30.48 | 184.15,30.48 C16.+ | 184.15,30.48 187.32,33.66 B1.+ 193.04,34.29 185.42,41.91 IC20.9
GND  (via drill 0.6, 0.8 pad 1.02)
  Top 1.016: IC19.8 171.45,67.31 176.53,62.23 186.69,62.23 187.96,63.5 | C16.- 186.69,39.37 193.04,39.37 X20.4 | IC21.22 134.62,35.56 137.16,38.1 143.51,38.1 X16.4 | IC4.8 26.67,67.31 30.48,63.5 C20.- 41.91,63.5 44.45,66.04 X2.4 | C21.- 41.91,40.64 X4.4 | 187.96,63.5 190.5,66.04 X18.4 | 187.96,63.5 C27.-
  Bottom 1.016: IC12.8 74.93,16.51 76.2,17.78 76.2,40.64 74.93,41.91 | 74.93,41.91 IC11.8 | 74.93,41.91 76.2,43.18 76.2,66.04 74.93,67.31 IC10.8 | C5.2 69.85,43.18 71.12,41.91 IC11.8 | C4.2 69.85,69.85 72.39,67.31 IC10.8 | C6.2 69.85,17.78 71.12,16.51 IC12.8 | IC19.8 171.45,67.31 172.72,66.04 172.72,43.18 171.45,41.91 IC20.8 167.64,41.91 166.37,43.18 C10.2 | IC16.8 119.38,41.91 118.11,43.18 C8.2 118.11,58.42 119.38,59.69 C24.- 120.65,63.5 121.92,64.77 IC15.8 119.38,67.31 118.11,68.58 C7.2 118.11,82.55 116.84,83.82 109.22,83.82 107.95,82.55 107.95,66.04 106.68,64.77 IC13.7 102.87,64.77 | 26.67,41.91 27.94,40.64 27.94,17.78 26.67,16.51 IC6.8 22.86,16.51 21.59,17.78 C3.2 | C9.2 166.37,69.85 168.91,67.31 IC19.8 | 26.67,41.91 IC5.8 | 26.67,41.91 27.94,43.18 27.94,66.04 26.67,67.31 | IC5.8 22.86,41.91 21.59,43.18 C2.2 | X4.4 50.8,40.64 53.34,38.1 | IC21.8 137.16,26.67 134.62,29.21 | 134.62,29.21 IC21.22 | 134.62,29.21 153.67,29.21 156.21,31.75 156.21,34.29 158.75,36.83 162.56,36.83 163.83,35.56 C15.2 | 101.6,40.64 102.87,39.37 IC14.7 105.41,34.29 106.68,33.02 108.94,33.02 S1.3 S1.4 109.5,27.66 109.22,27.94 104.14,27.94 101.6,25.4 101.6,16.51 100.33,15.24 X12.4 93.98,15.24 92.71,13.97 C28.- 76.2,13.97 IC12.8 | 101.6,40.64 X10.4 95.25,40.64 93.98,39.37 C23.- | IC18.7 148.59,39.37 147.32,40.64 148.59,40.64 149.86,41.91 149.86,60.96 IC17.7 | 102.87,64.77 101.6,66.04 X8.4 v93.98,66.04 92.71,64.77 C22.- | 102.87,64.77 102.87,41.91 101.6,40.64 | X14.4 138.43,66.04 C26.- 137.16,41.91 138.43,40.64 X16.4 | IC7.7 55.88,64.77 54.61,66.04 X2.4 | C1.2 21.59,68.58 22.86,67.31 IC4.8 | 26.67,67.31 27.94,68.58 27.94,86.36 26.67,87.63 7.62,87.63 6.35,86.36 6.35,66.04 7.62,64.77 IC1.7
  Bottom 1.016: IC3.7 11.43,13.97 15.24,10.16 48.26,10.16 49.53,8.89 57.15,8.89 59.69,6.35 102.87,6.35 107.95,11.43 127,11.43 128.27,12.7 | 26.67,67.31 IC4.8 | C17.- 24.13,38.1 25.4,39.37 IC5.8 | C13.- 24.13,63.5 25.4,64.77 IC4.8 | C18.- 72.39,63.5 73.66,64.77 IC10.8 | C19.- 72.39,38.1 73.66,39.37 IC11.8 | C25.- 168.91,63.5 170.18,64.77 IC19.8 | 128.27,12.7 SV1.7 SV1.8 | 128.27,12.7 129.54,11.43 156.21,11.43 165.1,20.32 165.1,22.86
  Bottom 1.27: IC21.8 C11.2 137.16,17.78 138.43,16.51 JP1.6 | X16.4 147.32,40.64 | IC18.7 149.86,39.37 | X6.4 52.07,15.24 | 52.07,15.24 53.34,13.97 IC9.7 59.69,13.97 62.23,11.43 72.39,11.43 73.66,12.7 IC12.8 | 7.62,39.37 IC2.7 | 7.62,39.37 6.35,38.1 6.35,15.24 7.62,13.97 IC3.7 | IC8.7 54.61,39.37 53.34,38.1 53.34,16.51 52.07,15.24 | IC1.7 6.35,62.23 6.35,40.64 7.62,39.37
  Bottom 1.778: 177.8,35.56 C14.2 | 177.8,35.56 179.07,36.83 C16.- | 170.18,39.37 173.99,39.37 177.8,35.56 | IC22.2 163.83,24.13 165.1,22.86 176.53,22.86 177.8,24.13
  Bottom 1.93: IC22.2 C15.2 | C14.2 IC23.2 177.8,24.13 179.07,22.86 192.41,22.86 B1.- | C12.- 170.18,39.37 IC20.8
  other vias: 40.64,69.85 40.64,72.39
  pour Bottom: 3.81,91.44 200.66,91.44 200.66,3.81 3.81,3.81
N$1
  Top 0.406: IC1.3 7.62,74.93 6.35,76.2 6.35,83.82 7.62,85.09 IC4.1
N$2
  Top 0.406: IC4.2 24.13,82.55 22.86,83.82 15.24,83.82 11.43,80.01 11.43,73.66 10.16,72.39 IC1.4
N$3
  Top 0.406: IC1.5 11.43,69.85 12.7,71.12 12.7,80.01 15.24,82.55 21.59,82.55 24.13,80.01 IC4.3
N$4
  Top 0.406: IC4.4 24.13,77.47 20.32,81.28 15.24,81.28 13.97,80.01 13.97,68.58 12.7,67.31 IC1.6
N$5
  Top 0.406: IC4.7 24.13,69.85 22.86,71.12 20.32,71.12 19.05,69.85 IC1.10
N$6
  Top 0.406: IC1.11 IC4.6
N$7
  Top 0.406: IC1.12 19.05,74.93 20.32,73.66 22.86,73.66 24.13,74.93 IC4.5
N$8
  Top 0.406: IC2.3 7.62,49.53 6.35,50.8 6.35,58.42 7.62,59.69 IC5.1
N$9
  Top 0.406: IC5.2 24.13,57.15 22.86,58.42 15.24,58.42 11.43,54.61 11.43,48.26 10.16,46.99 IC2.4
N$10
  Top 0.406: IC5.3 24.13,54.61 21.59,57.15 15.24,57.15 12.7,54.61 12.7,45.72 11.43,44.45 IC2.5
N$11
  Top 0.406: IC2.6 12.7,41.91 13.97,43.18 13.97,54.61 15.24,55.88 20.32,55.88 24.13,52.07 IC5.4
N$12
  Top 0.406: IC5.7 24.13,44.45 22.86,45.72 20.32,45.72 19.05,44.45 IC2.10
N$13
  Top 0.406: IC5.5 24.13,49.53 22.86,48.26 20.32,48.26 19.05,49.53 IC2.12
N$14
  Top 0.406: IC2.11 IC5.6
N$15
  Top 0.406: IC6.1 7.62,34.29 6.35,33.02 6.35,25.4 7.62,24.13 IC3.3
N$16
  Top 0.406: IC6.2 24.13,31.75 22.86,33.02 15.24,33.02 11.43,29.21 11.43,22.86 10.16,21.59 IC3.4
N$17
  Bottom 1.27: IC4.16 R1.1
N$18
  Bottom 1.27: IC4.15 R2.1
N$19
  Bottom 1.27: IC4.14 R3.1
N$20
  Bottom 1.27: IC4.13 R4.1
N$21
  Bottom 1.27: IC4.12 R5.1
N$22
  Bottom 1.27: IC4.11 R6.1
N$23
  Bottom 1.27: IC4.10 R7.1
N$24
  Bottom 1.016: R1.2 45.72,86.36 X1.1
N$25
  Bottom 1.016: R2.2 45.72,82.55 46.99,83.82 X1.2
N$26
  Bottom 1.016: R3.2 46.99,80.01 48.26,81.28 X1.3
N$27
  Bottom 1.016: R4.2 48.26,77.47 X1.4
N$28
  Bottom 1.016: R5.2 48.26,74.93 X2.1
N$29
  Bottom 1.016: R6.2 46.99,72.39 48.26,71.12 X2.2
N$30
  Bottom 1.016: R7.2 45.72,69.85 46.99,68.58 X2.3
N$31
  Bottom 1.27: IC5.16 R8.1
N$32
  Bottom 1.27: IC5.15 R9.1
N$33
  Bottom 1.27: IC5.14 R10.1
N$34
  Bottom 1.27: IC5.13 R11.1
N$35
  Bottom 1.27: IC5.12 R12.1
N$36
  Bottom 1.27: IC5.11 R13.1
N$37
  Bottom 1.27: IC5.10 R14.1
N$38
  Bottom 1.016: R8.2 45.72,60.96 X3.1
N$39
  Bottom 1.016: R9.2 45.72,57.15 46.99,58.42 X3.2
N$40
  Bottom 1.016: R10.2 46.99,54.61 48.26,55.88 X3.3
N$41
  Bottom 1.016: R11.2 48.26,52.07 X3.4
N$42
  Bottom 1.016: R12.2 48.26,49.53 X4.1
N$43
  Bottom 1.016: R13.2 46.99,46.99 48.26,45.72 X4.2
N$44
  Bottom 1.016: R14.2 45.72,44.45 46.99,43.18 X4.3
N$45
  Bottom 1.27: IC6.16 R15.1
N$46
  Bottom 1.27: IC6.15 R16.1
N$47
  Bottom 1.27: IC6.14 R17.1
N$48
  Bottom 1.27: IC6.13 R18.1
N$49
  Bottom 1.27: IC6.12 R19.1
N$50
  Bottom 1.27: IC6.11 R20.1
N$51
  Bottom 1.27: IC6.10 R21.1
N$52
  Bottom 1.016: R15.2 45.72,35.56 X5.1
N$53
  Bottom 1.016: R16.2 45.72,31.75 46.99,33.02 X5.2
N$54
  Bottom 1.016: R17.2 46.99,29.21 48.26,30.48 X5.3
N$55
  Bottom 1.016: R18.2 48.26,26.67 X5.4
N$56
  Bottom 1.016: R19.2 48.26,24.13 X6.1
N$57
  Bottom 1.016: R20.2 46.99,21.59 48.26,20.32 X6.2
N$58
  Bottom 1.016: R21.2 45.72,19.05 46.99,17.78 X6.3
N$59
  Top 0.406: SV1.1 SV1.2 120.65,20.32 121.92,21.59 IC21.2
N$60
  Top 0.406: SV1.3 SV1.4 123.19,20.32 124.46,21.59 IC21.3
N$61
  Top 0.406: IC3.5 11.43,19.05 12.7,20.32 12.7,29.21 15.24,31.75 21.59,31.75 24.13,29.21 IC6.3
N$62
  Top 0.406: IC6.4 24.13,26.67 20.32,30.48 15.24,30.48 13.97,29.21 13.97,17.78 12.7,16.51 IC3.6
N$63
  Top 0.406: IC6.7 24.13,19.05 22.86,20.32 20.32,20.32 19.05,19.05 IC3.10
N$64
  Top 0.406: IC6.5 24.13,24.13 22.86,22.86 20.32,22.86 19.05,24.13 IC3.12
N$65
  Top 0.406: IC3.11 IC6.6
N$66
  Bottom 1.016: IC10.16 R22.1
N$67
  Bottom 0.406: IC3.2 IC3.1 8.89,30.48 13.97,35.56 13.97,50.8 15.24,52.07 IC2.13
N$68
  Bottom 0.406: IC2.2 IC2.1 8.89,57.15 13.97,62.23 13.97,76.2 15.24,77.47 IC1.13
N$69
  Bottom 1.016: IC10.15 R23.1
N$70
  Bottom 1.016: IC10.14 R24.1
N$71
  Bottom 1.016: IC10.13 R25.1
N$72
  Bottom 1.016: IC10.12 R26.1
N$73
  Bottom 1.016: IC10.11 R27.1
N$74
  Bottom 1.016: IC10.10 R28.1
N$75
  Bottom 1.016: R22.2 93.98,86.36 X7.1
N$76
  Bottom 1.016: R23.2 93.98,82.55 95.25,83.82 X7.2
N$77
  Bottom 1.016: R24.2 95.25,80.01 96.52,81.28 X7.3
N$78
  Bottom 1.016: R25.2 96.52,77.47 X7.4
N$79
  Bottom 1.016: R26.2 96.52,74.93 X8.1
N$80
  Bottom 1.016: R27.2 93.98,72.39 95.25,71.12 X8.2
N$81
  Bottom 1.016: R28.2 93.98,68.58 X8.3
N$82
  Bottom 1.016: IC11.16 R29.1
N$83
  Bottom 1.016: IC11.15 R30.1
N$84
  Bottom 1.016: IC11.14 R31.1
N$85
  Bottom 1.016: IC11.13 R32.1
N$86
  Bottom 1.016: IC11.12 R33.1
N$87
  Bottom 1.016: IC11.11 R34.1
N$88
  Bottom 1.016: IC11.10 R35.1
N$89
  Bottom 1.016: R29.2 93.98,60.96 X9.1
N$90
  Bottom 1.016: R30.2 93.98,57.15 95.25,58.42 X9.2
N$91
  Bottom 1.016: R31.2 95.25,54.61 96.52,55.88 X9.3
N$92
  Bottom 1.016: R32.2 96.52,52.07 X9.4
N$93
  Bottom 1.016: R33.2 96.52,49.53 X10.1
N$94
  Bottom 1.016: R34.2 95.25,46.99 96.52,45.72 X10.2
N$95
  Bottom 1.016: R35.2 93.98,44.45 95.25,43.18 X10.3
N$96
  Bottom 1.016: IC12.16 R36.1
N$97
  Bottom 1.016: IC12.15 R37.1
N$98
  Bottom 1.016: IC12.14 R38.1
N$99
  Bottom 1.016: IC12.13 R39.1
N$100
  Bottom 1.016: IC12.12 R40.1
N$101
  Bottom 1.016: IC12.11 R41.1
N$102
  Bottom 1.016: IC12.10 R42.1
N$103
  Bottom 1.016: R36.2 93.98,35.56 X11.1
N$104
  Bottom 1.016: R37.2 93.98,31.75 95.25,33.02 X11.2
N$105
  Bottom 1.016: R38.2 95.25,29.21 96.52,30.48 X11.3
N$106
  Bottom 1.016: R39.2 96.52,26.67 X11.4
N$107
  Bottom 1.016: R40.2 96.52,24.13 X12.1
N$108
  Bottom 1.016: R41.2 95.25,21.59 96.52,20.32 X12.2
N$109
  Bottom 1.016: R42.2 93.98,19.05 95.25,17.78 X12.3
N$110
  Bottom 0.406: IC9.2 IC9.1 57.15,31.75 62.23,36.83 62.23,50.8 63.5,52.07 IC8.13
N$111
  Bottom 0.406: IC8.2 IC8.1 57.15,57.15 62.23,62.23 62.23,76.2 63.5,77.47 IC7.13
N$112
  Bottom 1.016: IC15.16 R43.1
N$113
  Top 0.406: SV1.5 SV1.6 125.73,20.32 127,21.59 130.81,21.59 132.08,22.86 IC21.6
N$114
  Top 0.406: IC7.6 60.96,67.31 62.23,68.58 62.23,80.01 63.5,81.28 68.58,81.28 72.39,77.47 IC10.4
N$115
  Top 0.406: IC7.5 59.69,69.85 60.96,71.12 60.96,81.28 62.23,82.55 69.85,82.55 72.39,80.01 IC10.3
N$116
  Top 0.406: IC7.4 58.42,72.39 59.69,73.66 59.69,82.55 60.96,83.82 71.12,83.82 72.39,82.55 IC10.2
N$117
  Top 0.406: IC7.3 55.88,74.93 54.61,76.2 54.61,81.28 55.88,82.55 58.42,82.55 60.96,85.09 IC10.1
N$118
  Top 0.406: IC7.10 66.04,69.85 67.31,71.12 71.12,71.12 72.39,69.85 IC10.7
N$119
  Top 0.406: IC7.11 IC10.6
N$120
  Top 0.406: IC7.12 66.04,74.93 67.31,73.66 71.12,73.66 72.39,74.93 IC10.5
N$121
  Top 0.406: IC11.1 55.88,59.69 54.61,58.42 54.61,50.8 55.88,49.53 IC8.3
N$122
  Top 0.406: IC8.4 58.42,46.99 59.69,48.26 59.69,54.61 63.5,58.42 71.12,58.42 72.39,57.15 IC11.2
N$123
  Top 0.406: IC8.5 59.69,44.45 60.96,45.72 60.96,54.61 63.5,57.15 69.85,57.15 72.39,54.61 IC11.3
N$124
  Top 0.406: IC8.6 60.96,41.91 62.23,43.18 62.23,54.61 63.5,55.88 68.58,55.88 72.39,52.07 IC11.4
N$125
  Top 0.406: IC11.7 72.39,44.45 71.12,45.72 67.31,45.72 66.04,44.45 IC8.10
N$126
  Top 0.406: IC8.12 66.04,49.53 67.31,48.26 71.12,48.26 72.39,49.53 IC11.5
N$127
  Top 0.406: IC8.11 IC11.6
N$128
  Top 0.406: IC9.3 55.88,24.13 54.61,25.4 54.61,33.02 55.88,34.29 IC12.1
N$129
  Top 0.406: IC9.4 58.42,21.59 59.69,22.86 59.69,29.21 63.5,33.02 71.12,33.02 72.39,31.75 IC12.2
N$130
  Top 0.406: IC9.5 59.69,19.05 60.96,20.32 60.96,29.21 63.5,31.75 69.85,31.75 72.39,29.21 IC12.3
N$131
  Top 0.406: IC9.6 60.96,16.51 62.23,17.78 62.23,29.21 63.5,30.48 68.58,30.48 72.39,26.67 IC12.4
N$132
  Top 0.406: IC9.10 66.04,19.05 67.31,20.32 71.12,20.32 72.39,19.05 IC12.7
N$133
  Top 0.406: IC9.12 66.04,24.13 67.31,22.86 72.39,22.86 IC12.5
N$134
  Top 0.406: IC9.11 IC12.6
N$135
  Bottom 1.016: IC15.15 R44.1
N$136
  Bottom 1.016: IC15.14 R45.1
N$137
  Bottom 1.016: IC15.13 R46.1
N$138
  Bottom 1.016: IC15.12 R47.1
N$139
  Bottom 1.016: IC15.11 R48.1
N$140
  Bottom 1.016: IC15.10 R49.1
N$141
  Bottom 1.016: R43.2 142.24,86.36 X13.1
N$142
  Bottom 1.016: R44.2 142.24,82.55 143.51,83.82 X13.2
N$143
  Bottom 1.016: R45.2 143.51,80.01 144.78,81.28 X13.3
N$144
  Bottom 1.016: R46.2 144.78,77.47 X13.4
N$145
  Bottom 1.016: R47.2 144.78,74.93 X14.1
N$146
  Bottom 1.016: R48.2 143.51,72.39 144.78,71.12 X14.2
N$147
  Bottom 1.016: R49.2 142.24,69.85 143.51,68.58 X14.3
N$148
  Bottom 1.016: IC16.16 R50.1
N$149
  Bottom 1.016: IC16.15 R51.1
N$150
  Bottom 1.016: IC16.14 R52.1
N$151
  Bottom 1.016: IC16.13 R53.1
N$152
  Bottom 1.016: IC16.12 R54.1
N$153
  Bottom 1.016: IC16.11 R55.1
N$154
  Bottom 1.016: IC16.10 R56.1
N$155
  Bottom 1.016: R50.2 142.24,60.96 X15.1
N$156
  Bottom 1.016: R51.2 142.24,57.15 143.51,58.42 X15.2
N$157
  Bottom 1.016: R52.2 143.51,54.61 144.78,55.88 X15.3
N$158
  Bottom 1.016: R53.2 144.78,52.07 X15.4
N$159
  Bottom 1.016: R54.2 144.78,49.53 X16.1
N$160
  Bottom 1.016: R55.2 143.51,46.99 144.78,45.72 X16.2
N$161
  Bottom 1.016: R56.2 142.24,44.45 143.51,43.18 X16.3
N$162
  Bottom 0.406: IC14.2 IC14.1 105.41,57.15 110.49,62.23 110.49,76.2 111.76,77.47 IC13.13
N$164
  Bottom 0.406: 1.27,93.98 203.2,93.98 203.2,1.27 1.27,1.27 1.27,93.98
N$165
  Top 0.406: IC15.7 120.65,69.85 119.38,71.12 115.57,71.12 114.3,69.85 IC13.10
N$166
  Top 0.406: IC15.5 120.65,74.93 119.38,73.66 115.57,73.66 114.3,74.93 IC13.12
N$167
  Top 0.406: IC13.11 IC15.6
N$168
  Top 0.406: IC14.10 114.3,44.45 115.57,45.72 119.38,45.72 120.65,44.45 IC16.7
N$169
  Top 0.406: IC16.5 120.65,49.53 119.38,48.26 115.57,48.26 114.3,49.53 IC14.12
N$170
  Top 0.406: IC14.11 IC16.6
N$171
  Top 0.406: IC15.1 104.14,85.09 102.87,83.82 102.87,76.2 104.14,74.93 IC13.3
N$172
  Top 0.406: IC13.4 106.68,72.39 107.95,73.66 107.95,80.01 111.76,83.82 119.38,83.82 120.65,82.55 IC15.2
N$173
  Top 0.406: IC13.5 107.95,69.85 109.22,71.12 109.22,80.01 111.76,82.55 118.11,82.55 120.65,80.01 IC15.3
N$174
  Top 0.406: IC13.6 109.22,67.31 110.49,68.58 110.49,80.01 111.76,81.28 116.84,81.28 120.65,77.47 IC15.4
N$175
  Top 0.406: IC16.1 104.14,59.69 102.87,58.42 102.87,50.8 104.14,49.53 IC14.3
N$176
  Top 0.406: IC14.4 106.68,46.99 107.95,48.26 107.95,54.61 111.76,58.42 119.38,58.42 120.65,57.15 IC16.2
N$177
  Top 0.406: IC14.5 107.95,44.45 109.22,45.72 109.22,54.61 111.76,57.15 118.11,57.15 120.65,54.61 IC16.3
N$178
  Top 0.406: IC16.4 120.65,52.07 116.84,55.88 111.76,55.88 110.49,54.61 110.49,43.18 109.22,41.91 IC14.6
N$179
  Bottom 1.016: IC19.16 R57.1
N$180
  Bottom 1.016: IC19.15 R58.1
N$181
  Bottom 1.016: IC19.14 R59.1
N$182
  Bottom 1.016: IC19.13 R60.1
N$183
  Bottom 1.016: IC19.12 R61.1
N$184
  Bottom 1.016: IC19.11 R62.1
N$185
  Bottom 1.016: IC19.10 R63.1
N$186
  Bottom 1.016: R57.2 190.5,86.36 X17.1
N$187
  Bottom 1.016: R58.2 190.5,82.55 191.77,83.82 X17.2
N$188
  Bottom 1.016: R59.2 191.77,80.01 193.04,81.28 X17.3
N$189
  Bottom 1.016: R60.2 193.04,77.47 X17.4
N$190
  Bottom 1.016: R61.2 193.04,74.93 X18.1
N$191
  Bottom 1.016: R62.2 191.77,72.39 193.04,71.12 X18.2
N$192
  Bottom 1.016: R63.2 190.5,69.85 191.77,68.58 X18.3
N$193
  Bottom 1.016: IC20.16 R64.1
N$194
  Bottom 1.016: IC20.15 R65.1
N$195
  Bottom 1.016: IC20.14 R66.1
N$196
  Bottom 1.016: IC20.13 R67.1
N$197
  Bottom 1.016: IC20.12 R68.1
N$198
  Bottom 1.016: IC20.11 R69.1
N$199
  Bottom 1.016: IC20.10 R70.1
N$200
  Bottom 1.016: R64.2 190.5,60.96 X19.1
N$201
  Bottom 1.016: R65.2 190.5,57.15 191.77,58.42 X19.2
N$202
  Bottom 1.016: R66.2 191.77,54.61 193.04,55.88 X19.3
N$203
  Bottom 1.016: R67.2 193.04,52.07 X19.4
N$204
  Bottom 1.016: R68.2 193.04,49.53 X20.1
N$205
  Bottom 1.016: R69.2 191.77,46.99 193.04,45.72 X20.2
N$206
  Bottom 1.016: R70.2 190.5,44.45 191.77,43.18 X20.3
N$207
  Bottom 0.406: IC18.2 IC18.1 153.67,57.15 158.75,62.23 158.75,76.2 160.02,77.47 IC17.13
N$208  (via drill 0.6, 0.8 pad 1.02)
  Top 0.406: v146.05,63.5 138.43,63.5 137.16,62.23 137.16,40.64 135.89,39.37 v133.35,39.37
  Bottom 0.406: IC17.1 IC17.2 152.4,77.47 151.13,76.2 151.13,66.04 148.59,63.5 v146.05,63.5 | IC14.13 110.49,52.07 109.22,50.8 109.22,38.1 110.49,36.83 114.3,36.83 116.84,39.37 v133.35,39.37
N$209
  Top 0.406: IC21.18 144.78,30.48 146.05,29.21 153.67,29.21 156.21,26.67 156.21,22.86 153.67,20.32 JP1.1
N$210
  Top 0.406: IC19.7 168.91,69.85 167.64,71.12 163.83,71.12 162.56,69.85 IC17.10
N$211
  Top 0.406: IC19.5 168.91,74.93 167.64,73.66 163.83,73.66 162.56,74.93 IC17.12
N$212
  Top 0.406: IC17.11 IC19.6
N$213
  Top 0.406: IC20.7 168.91,44.45 167.64,45.72 163.83,45.72 162.56,44.45 IC18.10
N$214
  Top 0.406: IC20.5 168.91,49.53 167.64,48.26 163.83,48.26 162.56,49.53 IC18.12
N$215
  Top 0.406: IC18.11 IC20.6
N$216
  Top 0.406: IC19.1 152.4,85.09 151.13,83.82 151.13,76.2 152.4,74.93 IC17.3
N$217
  Top 0.406: IC17.4 154.94,72.39 156.21,73.66 156.21,80.01 160.02,83.82 167.64,83.82 168.91,82.55 IC19.2
N$218
  Top 0.406: IC17.5 156.21,69.85 157.48,71.12 157.48,80.01 160.02,82.55 166.37,82.55 168.91,80.01 IC19.3
N$219
  Top 0.406: IC19.4 168.91,77.47 165.1,81.28 160.02,81.28 158.75,80.01 158.75,68.58 157.48,67.31 IC17.6
N$220
  Top 0.406: IC20.1 152.4,59.69 151.13,58.42 151.13,50.8 152.4,49.53 IC18.3
N$221
  Top 0.406: IC18.4 154.94,46.99 156.21,48.26 156.21,54.61 160.02,58.42 167.64,58.42 168.91,57.15 IC20.2
N$222
  Top 0.406: IC18.5 156.21,44.45 157.48,45.72 157.48,54.61 160.02,57.15 166.37,57.15 168.91,54.61 IC20.3
N$223
  Top 0.406: IC20.4 168.91,52.07 165.1,55.88 160.02,55.88 158.75,54.61 158.75,43.18 157.48,41.91 IC18.6
N$224
  Top 0.406: IC21.17 147.32,31.75 148.59,30.48 153.67,30.48 157.48,26.67 157.48,15.24 156.21,13.97 152.4,13.97 151.13,15.24 JP1.4
N$225
  Top 0.406: IC21.19 142.24,29.21 143.51,27.94 153.67,27.94 154.94,26.67 154.94,22.86 153.67,21.59 152.4,21.59 151.13,20.32 JP1.3
N$226  (1 unrouted)
  Top 0.406: JP1.5 135.89,19.05 133.35,16.51 133.35,8.89 132.08,7.62 105.41,7.62 104.14,8.89 104.14,20.32 105.41,21.59 | R71.1 105.41,30.48 102.87,27.94 102.87,24.13 105.41,21.59 | 105.41,21.59 111.76,21.59 114.3,24.13 | 114.3,24.13 114.3,25.68 S1.2 | IC21.1 119.38,24.13 118.11,22.86 115.57,22.86 114.3,24.13
N$227
  Bottom 1.27: IC22.1 170.18,27.94 IC23.3
  Bottom 1.93: IC23.3 C14.1 | 170.18,27.94 C12.+
N$228
  Bottom 2.54: J1.3 195.58,11.43 198.12,13.97 198.12,27.94 196.85,29.21 193.67,29.21 B1.AC2
N$229
  Top 2.54: J1.1 187.96,11.43 186.69,12.7 186.69,17.78 187.96,19.05 196.85,19.05 198.12,20.32 198.12,24.13 196.85,25.4 193.67,25.4 B1.AC1
PORTC0  (via drill 0.6)
  Top 0.406: IC21.23 132.08,36.83 130.81,38.1 127,38.1 125.73,39.37 125.73,86.36 124.46,87.63 106.68,87.63 v105.41,86.36
  Bottom 0.406: IC13.2 IC13.1 v105.41,86.36
PORTC1
  Top 0.406: IC17.8 161.29,63.5 160.02,62.23 151.13,62.23 | 151.13,62.23 149.86,63.5 149.86,87.63 148.59,88.9 102.87,88.9 101.6,87.63 101.6,64.77 104.14,62.23 111.76,62.23 113.03,63.5 | IC18.8 161.29,38.1 160.02,36.83 151.13,36.83 149.86,38.1 149.86,60.96 151.13,62.23 | IC21.24 129.54,34.29 124.46,39.37 IC14.8 123.19,39.37 124.46,40.64 124.46,60.96 123.19,62.23 120.65,62.23 119.38,60.96 115.57,60.96 113.03,63.5 | 113.03,63.5 IC13.8
PORTC2  (via drill 0.6)
  Top 0.406: IC21.25 127,34.29 123.19,38.1 115.57,38.1 114.3,36.83 102.87,36.83 101.6,38.1 95.25,38.1 93.98,36.83 80.01,36.83 77.47,39.37 77.47,86.36 76.2,87.63 72.39,87.63 71.12,86.36 59.69,86.36 v57.15,83.82
  Bottom 0.406: IC7.2 IC7.1 v57.15,83.82
PORTC3  (via drill 0.8 pad 0.41)
  Top 0.406: IC21.26 124.46,34.29 121.92,36.83 118.11,36.83 116.84,35.56 105.41,35.56 101.6,31.75 101.6,11.43 100.33,10.16 91.44,10.16 90.17,8.89 83.82,8.89 82.55,10.16 7.62,10.16 5.08,12.7 5.08,59.69 6.35,60.96 10.16,60.96 v11.43,62.23
  Bottom 0.406: IC1.1 IC1.2 10.16,77.47 11.43,76.2 v11.43,62.23
PORTC4  (via drill 0.6)
  Top 0.406: IC7.8 64.77,63.5 62.23,60.96 55.88,60.96 53.34,58.42 53.34,40.64 52.07,39.37 | IC8.8 64.77,38.1 63.5,36.83 54.61,36.83 | 54.61,36.83 52.07,39.37 | IC9.8 64.77,12.7 63.5,11.43 54.61,11.43 53.34,12.7 | 53.34,12.7 53.34,35.56 54.61,36.83 | IC3.8 17.78,13.97 19.05,12.7 53.34,12.7 | v11.43,36.83 15.24,36.83 16.51,38.1 IC2.8 17.78,39.37 19.05,40.64 22.86,40.64 24.13,39.37 29.21,39.37 31.75,36.83 43.18,36.83 44.45,38.1 50.8,38.1 52.07,39.37
  Bottom 0.406: IC1.8 16.51,62.23 11.43,57.15 v11.43,36.83

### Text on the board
Bottom: Taller de Electronica 2010 | Control Display - Parqueadero Santo Domingo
